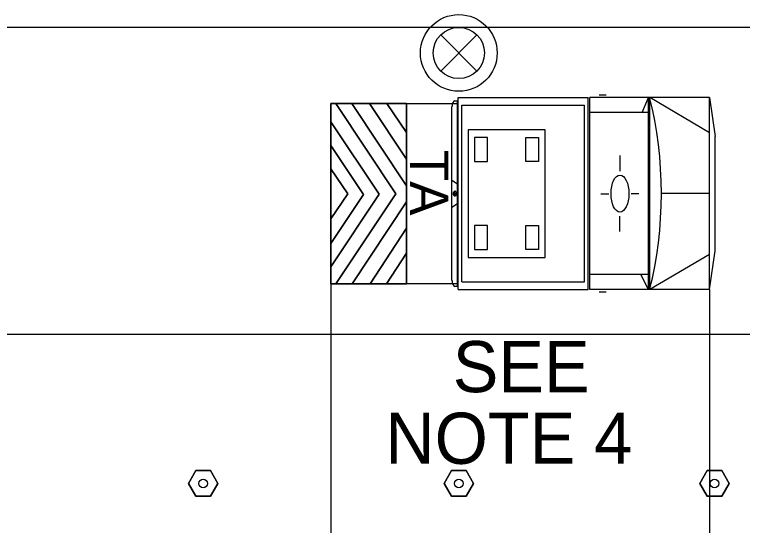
# Model space of a CAD drawing. Extents: x 99958 to 100176, y 99935 to 100011.
# Drawn here: x 100009.069 to 100010.207, y 99974.837 to 99975.636 of the extents above; entities that cross this region are included whole.
import ezdxf

# ---------------------------------------------------------------- set-up
doc = ezdxf.new("R2010")
doc.units = 0
for name, color, linetype in [('RD_MK_LineEdgeWhite', 7, 'Continuous'), ('RD_MK_LineLane', 7, 'Continuous'), ('TR_WZ_TrafficSafetyDrum', 7, 'Continuous'), ('TR_WZ_TransportableAttenuator', 7, 'Continuous'), ('TR_WZ_TubularMarker', 7, 'Continuous'), ('TR_WZ_WorkZoneDetails', 7, 'Continuous'), ('TR_WZ_WorkZoneTextCurrent', 7, 'Continuous')]:
    doc.layers.add(name, color=color, linetype=linetype)

msp = doc.modelspace()

# ---------------------------------------------------------------- linework, layer by layer
at = {"layer": 'RD_MK_LineEdgeWhite'}
msp.add_line((100000.8283, 99975.1357), (100014.8933, 99975.1357), dxfattribs=at)
at = {"layer": 'RD_MK_LineLane'}
msp.add_lwpolyline([(100014.8933, 99975.6157), (100000.8283, 99975.6157)], dxfattribs=at)
at = {"layer": 'TR_WZ_TrafficSafetyDrum'}
for p, q in [((100009.7353, 99975.604), (100009.7919, 99975.5474)), ((100009.7919, 99975.604), (100009.7353, 99975.5474))]:
    msp.add_line(p, q, dxfattribs=at)
for radius in [0.06, 0.06, 0.04]:
    msp.add_circle((100009.7636, 99975.5757), radius, dxfattribs=at)
at = {"layer": 'TR_WZ_TransportableAttenuator'}
for p, q in [((100009.9943, 99975.5099), (100009.983, 99975.5099)), ((100009.5964, 99975.4965), (100009.5713, 99975.4965)), ((100009.5713, 99975.4965), (100009.6651, 99975.3555)), ((100009.6651, 99975.3555), (100009.5713, 99975.4965)), ((100009.5713, 99975.4965), (100009.5964, 99975.4965)), ((100009.6818, 99975.3681), (100009.5964, 99975.4965)), ((100009.5964, 99975.4965), (100009.6818, 99975.3681)), ((100009.651, 99975.4965), (100009.624, 99975.4965)), ((100009.624, 99975.4965), (100009.6818, 99975.4096)), ((100009.6818, 99975.4096), (100009.624, 99975.4965)), ((100009.624, 99975.4965), (100009.651, 99975.4965)), ((100009.6818, 99975.4511), (100009.651, 99975.4965)), ((100009.651, 99975.4965), (100009.6818, 99975.4511)), ((100009.7625, 99975.4962), (100009.6818, 99975.4962)), ((100009.6818, 99975.4962), (100009.6818, 99975.2146)), ((100009.7574, 99975.5008), (100009.7618, 99975.5008)), ((100009.7618, 99975.2107), (100009.7618, 99975.5008)), ((100009.7625, 99975.5058), (100009.966, 99975.5058)), ((100009.7625, 99975.2058), (100009.7625, 99975.5058)), ((100009.7625, 99975.2151), (100009.7625, 99975.4962)), ((100009.966, 99975.2058), (100009.966, 99975.5058)), ((100009.9688, 99975.2058), (100009.9688, 99975.5058)), ((100010.1557, 99975.5058), (100009.9688, 99975.5058)), ((100010.0507, 99975.4825), (100010.0605, 99975.5058)), ((100010.0605, 99975.2058), (100010.0605, 99975.5058)), ((100010.0622, 99975.2058), (100010.0622, 99975.5058)), ((100010.1557, 99975.4508), (100010.0622, 99975.5058)), ((100010.1557, 99975.2058), (100010.1557, 99975.5058)), ((100010.1557, 99975.5058), (100010.1649, 99975.4452)), ((100009.7529, 99975.2198), (100009.7529, 99975.4917)), ((100009.7682, 99975.2177), (100009.7682, 99975.4938)), ((100009.7682, 99975.4938), (100009.9603, 99975.4938)), ((100009.9603, 99975.2177), (100009.9603, 99975.4938)), ((100010.0605, 99975.4825), (100009.9688, 99975.4825)), ((100009.6389, 99975.3546), (100009.5636, 99975.4678)), ((100009.5636, 99975.4678), (100009.5636, 99975.431)), ((100009.5636, 99975.431), (100009.5636, 99975.4678)), ((100009.5636, 99975.4678), (100009.6389, 99975.3546)), ((100009.6818, 99975.4096), (100009.6818, 99975.4511)), ((100009.6818, 99975.4511), (100009.6818, 99975.4096)), ((100010.1649, 99975.2663), (100010.1649, 99975.4452)), ((100009.5636, 99975.431), (100009.6147, 99975.3542)), ((100009.6147, 99975.3542), (100009.5636, 99975.431)), ((100010.0157, 99975.4152), (100010.0157, 99975.391)), ((100009.5898, 99975.3553), (100009.5636, 99975.3945)), ((100009.5636, 99975.3945), (100009.5636, 99975.3165)), ((100009.5636, 99975.3945), (100009.5898, 99975.3553)), ((100009.5636, 99975.3165), (100009.5636, 99975.3945)), ((100009.7529, 99975.3769), (100009.7618, 99975.3712)), ((100009.6818, 99975.343), (100009.6818, 99975.3681)), ((100009.6818, 99975.3681), (100009.6818, 99975.343)), ((100009.7574, 99975.3515), (100009.7574, 99975.36)), ((100009.5636, 99975.3165), (100009.5898, 99975.3553)), ((100009.5898, 99975.3553), (100009.5636, 99975.3165)), ((100009.5636, 99975.2414), (100009.6389, 99975.3546)), ((100009.6389, 99975.3546), (100009.5636, 99975.2414)), ((100009.6147, 99975.3542), (100009.5636, 99975.2779)), ((100009.5636, 99975.2779), (100009.6147, 99975.3542)), ((100009.6651, 99975.3555), (100009.5714, 99975.2146)), ((100009.5714, 99975.2146), (100009.6651, 99975.3555)), ((100009.7553, 99975.3557), (100009.7594, 99975.3557)), ((100009.9858, 99975.3555), (100009.9983, 99975.3556)), ((100010.0017, 99975.3563), (100010.0017, 99975.3563)), ((100010.0455, 99975.3555), (100010.033, 99975.3556)), ((100010.1557, 99975.3557), (100010.0806, 99975.3557)), ((100009.597, 99975.2146), (100009.6818, 99975.343)), ((100009.6818, 99975.343), (100009.597, 99975.2146)), ((100009.7529, 99975.3346), (100009.7618, 99975.3402)), ((100010.0157, 99975.2963), (100010.0157, 99975.3205)), ((100009.6818, 99975.3015), (100009.6247, 99975.2146)), ((100009.6247, 99975.2146), (100009.6818, 99975.3015)), ((100009.6818, 99975.2623), (100009.6818, 99975.3015)), ((100009.6818, 99975.3015), (100009.6818, 99975.2623)), ((100009.5636, 99975.2779), (100009.5636, 99975.2414)), ((100009.5636, 99975.2414), (100009.5636, 99975.2779)), ((100009.6502, 99975.2146), (100009.6818, 99975.2623)), ((100009.6818, 99975.2623), (100009.6502, 99975.2146)), ((100010.1557, 99975.2607), (100010.0622, 99975.2058)), ((100010.1557, 99975.2058), (100010.1649, 99975.2663)), ((100010.0605, 99975.229), (100009.9688, 99975.229)), ((100010.0605, 99975.2058), (100010.0486, 99975.229)), ((100009.5714, 99975.2146), (100009.597, 99975.2146)), ((100009.597, 99975.2146), (100009.5714, 99975.2146)), ((100009.6247, 99975.2146), (100009.6502, 99975.2146)), ((100009.6502, 99975.2146), (100009.6247, 99975.2146)), ((100009.7625, 99975.2146), (100009.6818, 99975.2146)), ((100009.7574, 99975.2107), (100009.7618, 99975.2107)), ((100009.7682, 99975.2177), (100009.9603, 99975.2177)), ((100009.7625, 99975.2058), (100009.966, 99975.2058)), ((100010.1557, 99975.2058), (100009.9688, 99975.2058)), ((100009.9943, 99975.2015), (100009.983, 99975.2015))]:
    msp.add_line(p, q, dxfattribs=at)
for points in [[(100009.6818, 99975.4965), (100009.5636, 99975.4965), (100009.5636, 99975.2146), (100009.6818, 99975.2146)], [(100009.7783, 99975.2557), (100009.8985, 99975.2557), (100009.8985, 99975.4557), (100009.7783, 99975.4557)], [(100009.7883, 99975.4057), (100009.8083, 99975.4057), (100009.8083, 99975.4432), (100009.7883, 99975.4432)], [(100009.8885, 99975.4057), (100009.8685, 99975.4057), (100009.8685, 99975.4432), (100009.8885, 99975.4432)], [(100009.7883, 99975.2682), (100009.8083, 99975.2682), (100009.8083, 99975.3057), (100009.7883, 99975.3057)], [(100009.8885, 99975.2682), (100009.8685, 99975.2682), (100009.8685, 99975.3057), (100009.8885, 99975.3057)]]:
    msp.add_lwpolyline(points, close=True, dxfattribs=at)
msp.add_lwpolyline([(100009.6818, 99975.2146), (100009.5636, 99975.2146), (100009.5636, 99975.4965), (100009.6818, 99975.4962)], dxfattribs=at)
for centre, major_axis, start_param, end_param in [((100009.7574, 99975.4917), (0, 0.00916), 0, 1.570796), ((100009.9286, 99975.3558), (0, 0.3148), 4.215667, 5.208926), ((100009.7574, 99975.2198), (0, -0.00916), 4.712389, 6.283185)]:
    msp.add_ellipse(centre, major_axis=major_axis, ratio=0.482618, start_param=start_param, end_param=end_param, dxfattribs=at)
for centre, major_axis in [((100010.0157, 99975.3557), (0, -0.0289)), ((100009.7574, 99975.3557), (0, -0.00423))]:
    msp.add_ellipse(centre, major_axis=major_axis, ratio=0.482618, dxfattribs=at)
at = {"layer": 'TR_WZ_TubularMarker'}
for points in [[(100009.3405, 99974.9024), (100009.3521, 99974.9224), (100009.3752, 99974.9224), (100009.3867, 99974.9024), (100009.3752, 99974.8824), (100009.3521, 99974.8824)], [(100009.7405, 99974.9024), (100009.7521, 99974.9224), (100009.7752, 99974.9224), (100009.7867, 99974.9024), (100009.7752, 99974.8824), (100009.7521, 99974.8824)], [(100010.1405, 99974.9024), (100010.1521, 99974.9224), (100010.1752, 99974.9224), (100010.1867, 99974.9024), (100010.1752, 99974.8824), (100010.1521, 99974.8824)]]:
    msp.add_lwpolyline(points, close=True, dxfattribs=at)
for points in [[(100009.3521, 99974.8824), (100009.3752, 99974.8824), (100009.3867, 99974.9024), (100009.3752, 99974.9224), (100009.3521, 99974.9224), (100009.3405, 99974.9024), (100009.3521, 99974.8824)], [(100009.7521, 99974.8824), (100009.7752, 99974.8824), (100009.7867, 99974.9024), (100009.7752, 99974.9224), (100009.7521, 99974.9224), (100009.7405, 99974.9024), (100009.7521, 99974.8824)], [(100010.1521, 99974.8824), (100010.1752, 99974.8824), (100010.1867, 99974.9024), (100010.1752, 99974.9224), (100010.1521, 99974.9224), (100010.1405, 99974.9024), (100010.1521, 99974.8824)]]:
    msp.add_lwpolyline(points, dxfattribs=at)
for centre in [(100009.3636, 99974.9024), (100009.7636, 99974.9024), (100010.1636, 99974.9024)]:
    msp.add_circle(centre, 0.00667, dxfattribs=at)
at = {"layer": 'TR_WZ_WorkZoneDetails'}
for p, q in [((100009.5636, 99975.2146), (100009.5636, 99974.4957)), ((100010.1557, 99975.2058), (100010.1557, 99974.4957))]:
    msp.add_line(p, q, dxfattribs=at)

# ---------------------------------------------------------------- texts
at = {"layer": 'TR_WZ_TransportableAttenuator'}
msp.add_text('TA', height=0.06013, rotation=270, dxfattribs=at).set_placement((100009.6873, 99975.4243))
at = {"layer": 'TR_WZ_WorkZoneTextCurrent'}
for s, p in [('SEE', (100009.7541, 99975.0451)), ('NOTE 4', (100009.6485, 99974.9331))]:
    msp.add_text(s, height=0.08, dxfattribs=at).set_placement(p)

doc.saveas('drawing.dxf')
